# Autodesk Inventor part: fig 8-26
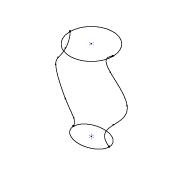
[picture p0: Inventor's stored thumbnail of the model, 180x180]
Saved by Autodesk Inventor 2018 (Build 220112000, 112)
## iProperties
Shininess: 64.0
Length Units: 11269
Angle Units: 11279
Time Units: 11290
Mass Units: 11283
Length Display Precision: 3
Angle Display Precision: 2
Compacted: True
Part Number: fig 8-26
Document SubType Name: Modeling
Created: 2002-12
Designer: deepak
Density: 1 g/cm^3
Material: Generic
Appearance: Default
Density: 0.0
Volumn: 0.0
Area: 0.0
PropertySet Name: Model Information
Control State: 0
Master: False
Checked Out: False
Author: deepak
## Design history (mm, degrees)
sketch "Sketch1"
  geometry: 2 further points; 1 other entity
  constraints: 1 coincident, 3 other
workplane "Work Plane1"
workplane "Work Plane2"
sketch "Sketch3"
  geometry: C1 r 60 at (0, 0); 1 further point
  constraints: 1 centre point, 1 coincident, 1 other
sketch "Sketch4"
  geometry: 8 further points
  constraints: 8 other
sketch "Sketch5"
  geometry: 6 further points
  constraints: 6 other
sketch "Sketch6"
  geometry: 6 further points
  constraints: 6 other
  dimensions: "d20" = 35 distance of point (0, 0) point (-35, 0); "d21" = 0 vertical distance of point (0, 0) point (-35, 0); "d22" = 225 vertical distance of point (0, 0) point (-60, 225); "d23" = 60 horizontal distance of point (0, 0) point (-60, 225); "d24" = 100 horizontal distance of point (0, 0) point (-100, 125); "d25" = 125 vertical distance of point (0, 0) point (-100, 125)
other parameters: "d5" = 125
